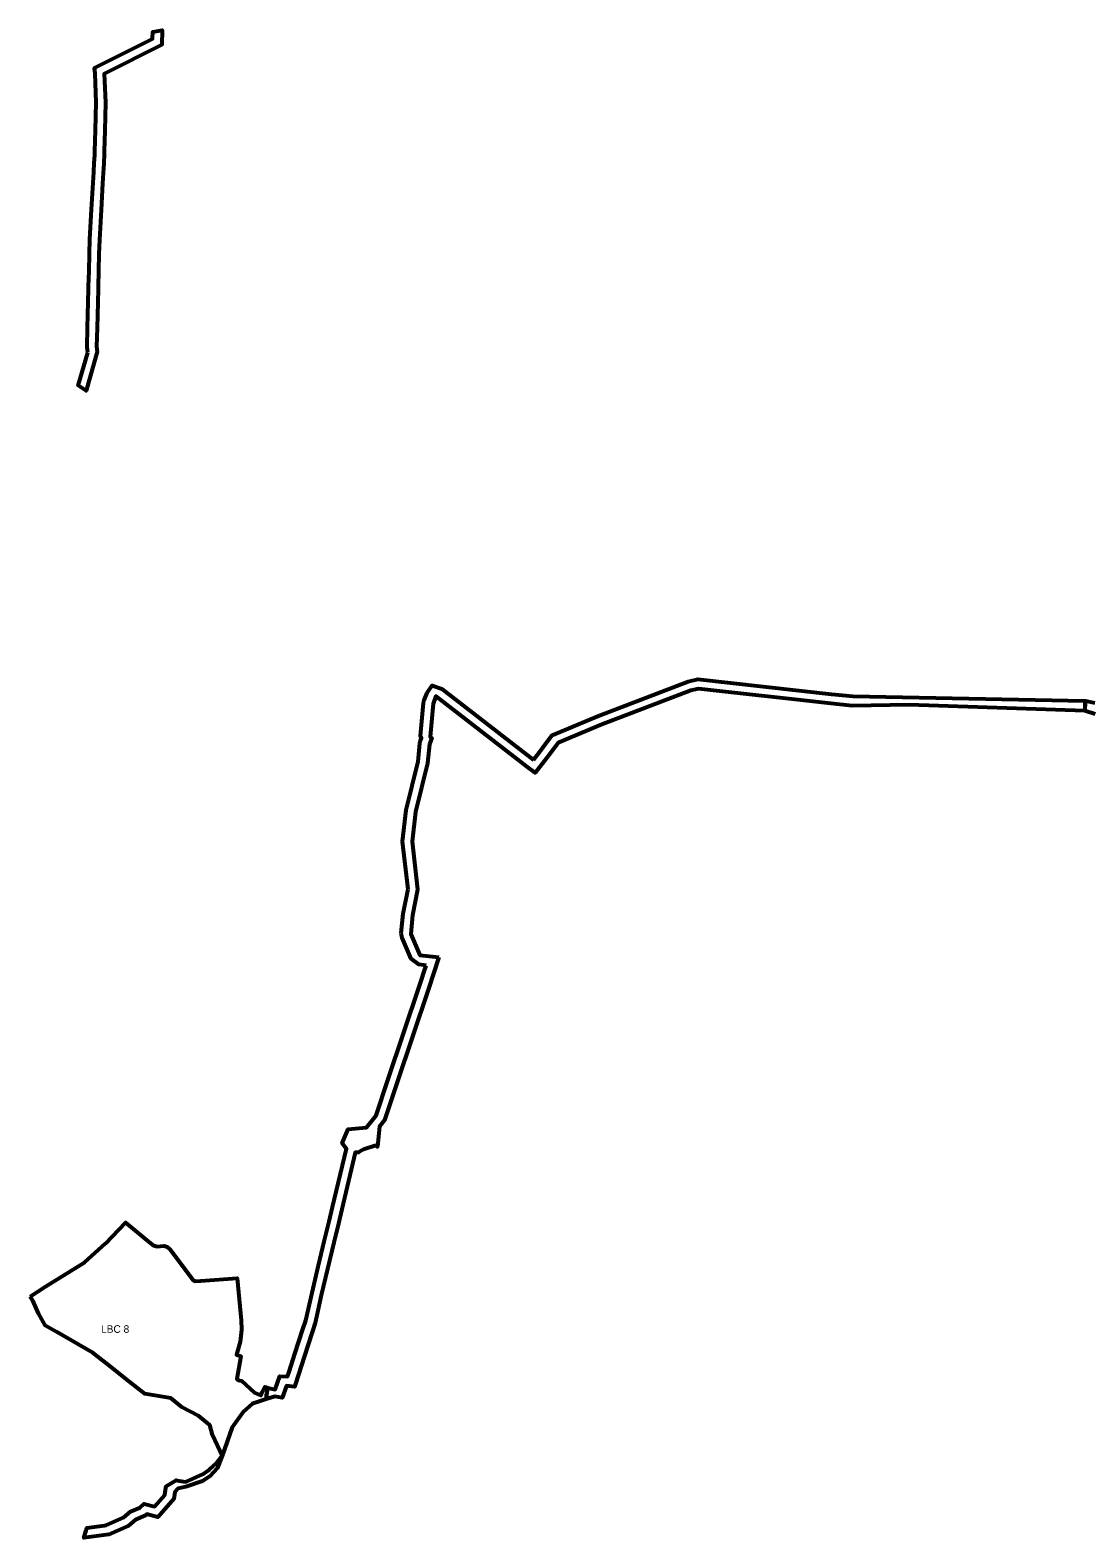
# Model space of a CAD drawing. Extents: x -650276 to -642570, y -1074314 to -1066553.
# Drawn here: x -649080 to -647403, y -1074314 to -1071929 of the extents above; entities that cross this region are included whole.
import ezdxf
from ezdxf.enums import TextEntityAlignment as Align

# ---------------------------------------------------------------- set-up
doc = ezdxf.new("R2010")
doc.units = 0
doc.header["$LTSCALE"] = 4.8
doc.layers.add('23', color=7, linetype='Continuous', lineweight=53)
doc.layers.add('27', color=7, linetype='Continuous', lineweight=53)
doc.layers.add('63', color=7, linetype='Continuous')

msp = doc.modelspace()

# ---------------------------------------------------------------- linework, layer by layer
at = {"layer": '23'}
msp.add_lwpolyline([(-649079.5, -1073932.07), (-649055.44, -1073915.89), (-648992.83, -1073877.83), (-648960.55, -1073848.32), (-648928.87, -1073814.72), (-648889.36, -1073847.76), (-648884.44, -1073851.12), (-648878.37, -1073852.91), (-648867.32, -1073851.76), (-648862.67, -1073853.45), (-648858.52, -1073857.16), (-648821.85, -1073905.87), (-648818.02, -1073907.85), (-648809.53, -1073907.19), (-648751.99, -1073902.72), (-648745.56, -1073969.15), (-648745.15, -1073984.75), (-648747.25, -1074003.7), (-648753.25, -1074024.17), (-648746.05, -1074026.17), (-648752.57, -1074061.85), (-648750.31, -1074064.07), (-648745.35, -1074065.36), (-648725.36, -1074083.48), (-648714.48, -1074088.54), (-648712.7, -1074083.01), (-648708.17, -1074075), (-648706.15, -1074075.52), (-648703.8, -1074076.13), (-648705.11, -1074083.13), (-648706.43, -1074094.32), (-648728.35, -1074101.69), (-648742.6, -1074114.47), (-648760.17, -1074138.5), (-648775.93, -1074183.91), (-648790.86, -1074151.18), (-648795.07, -1074135.39), (-648810.15, -1074123.44), (-648813.45, -1074120.68), (-648839.7, -1074106.68), (-648857.12, -1074092.9), (-648898.23, -1074085.75), (-648922.26, -1074067.06), (-648942.96, -1074050.62), (-648956.81, -1074039.24), (-648965.58, -1074032.41), (-648980.26, -1074020.98), (-649037.74, -1073987.98), (-649055.82, -1073977.54), (-649066.5, -1073958.76), (-649075.48, -1073938.46)], close=True, dxfattribs=at)
at = {"layer": '27'}
for points in [[(-648988.27, -1072439.04), (-648989.45, -1072430.27), (-648988.65, -1072399.86), (-648987.6, -1072359.77), (-648987.02, -1072337.8), (-648986.95, -1072334.96), (-648986.31, -1072310.66), (-648985.6, -1072283.43), (-648984.99, -1072260.16), (-648982.26, -1072212.8), (-648979.84, -1072170.82), (-648978.87, -1072154.04), (-648978.03, -1072139.48), (-648977.33, -1072127.34), (-648977.3, -1072126.08), (-648977.26, -1072124.65), (-648977.16, -1072120.58), (-648976.35, -1072087.75), (-648975.27, -1072044.01), (-648976.91, -1071998.2), (-648977.48, -1071989.2), (-648962.766, -1071981.81), (-648885.95, -1071943.23), (-648885.56, -1071932.1), (-648870.458, -1071929.441), (-648871.27, -1071952.643), (-648962.195, -1071998.309), (-648960.263, -1072043.893), (-648961.355, -1072088.12), (-648962.165, -1072120.949), (-648962.27, -1072125.223), (-648963.052, -1072140.301), (-648963.895, -1072154.905), (-648964.865, -1072171.684), (-648967.285, -1072213.663), (-648970.001, -1072260.788), (-648970.605, -1072283.823), (-648971.955, -1072335.341), (-648972.025, -1072338.183), (-648972.605, -1072360.164), (-648973.655, -1072400.254), (-648974.424, -1072429.462), (-648973.238, -1072438.27), (-648990.804, -1072500.016), (-649003.5, -1072491.347)], [(-648864.927, -1074234.687), (-648864.54, -1074231.96), (-648848.28, -1074222.49), (-648844.05, -1074223.24), (-648833.11, -1074225.2), (-648806.55, -1074212.62), (-648795.65, -1074205.35), (-648784.8, -1074195.26), (-648775.93, -1074183.91), (-648783.863, -1074204.056), (-648794.902, -1074216.219), (-648807.065, -1074223.704), (-648833.449, -1074232.685), (-648845.424, -1074235.305), (-648850.711, -1074241.264), (-648852.226, -1074251.935), (-648877.799, -1074280.64), (-648894.988, -1074276.254), (-648897.136, -1074278.294), (-648912.63, -1074284.912), (-648923.698, -1074294.313), (-648955.265, -1074308.325), (-648994.457, -1074313.539), (-648991.03, -1074301.92), (-648989.82, -1074297.79), (-648961.69, -1074294.05), (-648959.38, -1074293.74), (-648931.76, -1074281.48), (-648920.61, -1074272.01), (-648905.51, -1074265.56), (-648899.31, -1074259.67), (-648882.93, -1074263.85), (-648866.44, -1074245.34)]]:
    msp.add_lwpolyline(points, close=True, dxfattribs=at)
for points in [[(-648283.373, -1073083.159), (-648274.044, -1073071.212), (-648262.419, -1073055.602), (-648253.635, -1073044.348), (-648180.651, -1073013.629), (-648038.877, -1072959.418), (-648023.495, -1072955.875), (-647811.752, -1072979.4), (-647778.296, -1072982.767), (-647411.294, -1072989.813), (-647411.34, -1073005.89), (-647689.11, -1072996.49), (-647779.326, -1072997.739), (-647813.331, -1072994.317), (-648022.615, -1072971.065), (-648034.493, -1072973.802), (-648175.061, -1073027.551), (-648244.214, -1073056.657), (-648250.491, -1073064.698), (-648262.116, -1073080.308), (-648280.472, -1073103.814), (-648292.605, -1073094.981), (-648437.643, -1072982.601), (-648442.187, -1072994.5), (-648447.043, -1073046.967), (-648444.11, -1073048.69), (-648448.1, -1073058.393)], [(-648481.853, -1073287.675), (-648490.539, -1073212.35), (-648484.661, -1073162.812), (-648465.708, -1073085.876), (-648463.036, -1073057.011), (-648461.973, -1073052.688), (-648460.355, -1073048.753), (-648461.979, -1073045.585), (-648457.123, -1072993.118), (-648456.2, -1072989.149), (-648451.657, -1072977.25)], [(-648451.657, -1072977.25), (-648443.591, -1072965.983), (-648428.456, -1072970.744), (-648283.373, -1073083.159)], [(-647394.782, -1073011.002), (-647411.34, -1073005.89), (-647410.79, -1073001.1), (-647409.484, -1072990.206), (-647395.47, -1072993.25)], [(-648448.1, -1073058.393), (-648450.875, -1073088.375), (-648469.875, -1073165.5), (-648475.437, -1073212.375), (-648466.687, -1073288.25), (-648474.5, -1073328.75), (-648477.562, -1073358.875), (-648463.25, -1073392.125), (-648448.434, -1073393.794), (-648433.206, -1073395.51)], [(-648492.485, -1073357.358), (-648489.355, -1073326.567), (-648481.853, -1073287.675)], [(-648453.228, -1073408.349), (-648464.929, -1073407.031), (-648477.028, -1073398.055), (-648491.34, -1073364.805), (-648492.485, -1073357.358)], [(-648433.206, -1073395.51), (-648449.599, -1073445.278), (-648499.399, -1073594.679), (-648518.867, -1073652.836), (-648527, -1073663.06), (-648530.35, -1073695.22), (-648532.79, -1073693.1), (-648552.06, -1073699.58), (-648555.55, -1073701.12), (-648559.97, -1073704.24), (-648565.224, -1073704.393), (-648586.715, -1073794.059), (-648592.044, -1073816.692), (-648599.275, -1073846.445), (-648609.231, -1073888.415), (-648618.976, -1073929.605), (-648628.938, -1073973.771), (-648633.679, -1073988.276), (-648646.33, -1074027.404), (-648659.866, -1074069.929), (-648661.223, -1074074.71), (-648674.078, -1074073.329), (-648680.921, -1074092.335), (-648692.23, -1074090.17), (-648702.41, -1074093.15), (-648706.43, -1074094.32), (-648705.11, -1074083.13), (-648703.8, -1074076.13), (-648692.12, -1074079.16), (-648684.45, -1074057.86), (-648672.336, -1074058.391), (-648669.584, -1074051.005), (-648660.613, -1074022.822), (-648647.944, -1073983.639), (-648643.415, -1073969.782), (-648633.591, -1073926.228), (-648623.827, -1073884.957), (-648613.86, -1073842.943), (-648606.633, -1073813.202), (-648601.309, -1073790.592), (-648579.272, -1073698.648), (-648585.92, -1073689.3), (-648576.53, -1073667.04), (-648547.476, -1073664.705), (-648532.252, -1073645.567), (-648513.627, -1073589.927), (-648463.838, -1073440.559), (-648453.228, -1073408.349)]]:
    msp.add_lwpolyline(points, dxfattribs=at)

# ---------------------------------------------------------------- texts
at = {"layer": '63'}
msp.add_text('LBC 8', height=12, dxfattribs=at).set_placement((-648945.075, -1073989.353), align=Align.CENTER)

doc.saveas('drawing.dxf')
